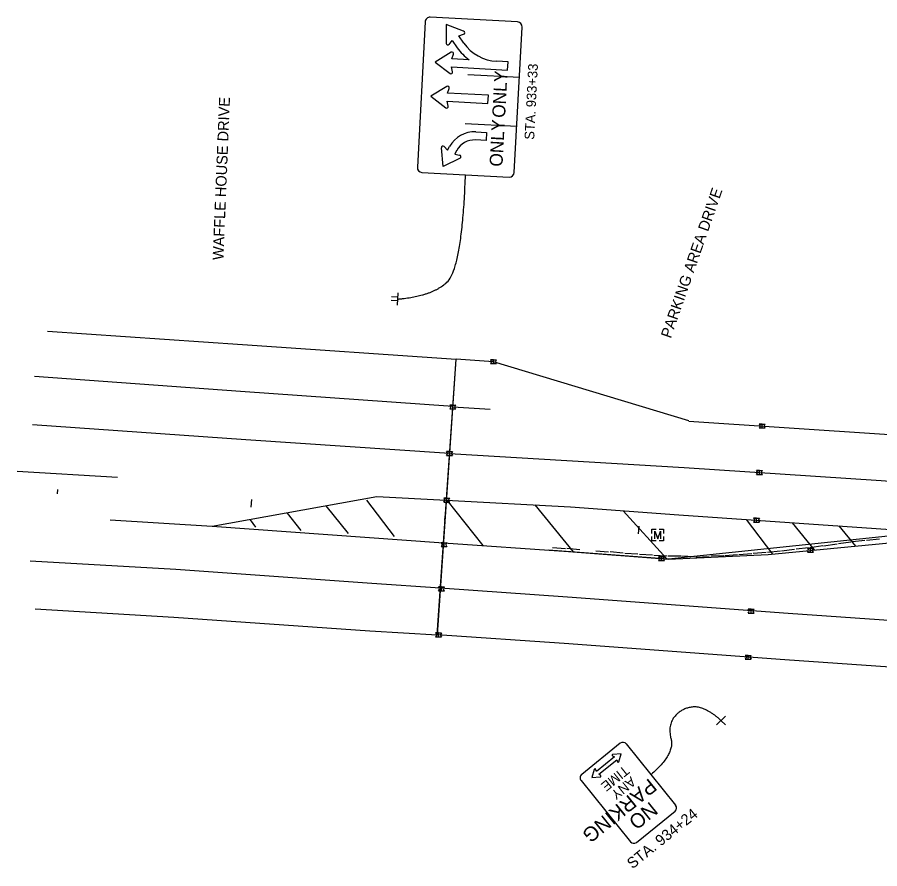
# Model space of a CAD drawing. Extents: x 1847379 to 1850904, y 217032 to 220169.
# Drawn here: x 1847379.5 to 1847601.7, y 218842.5 to 219061.8 of the extents above; entities that cross this region are included whole.
import ezdxf

# ---------------------------------------------------------------- set-up
doc = ezdxf.new("R2010")
doc.units = 0
for name, color, linetype in [('BR_P_Gen_Approach_Slab_Hidden', 7, 'Continuous'), ('BR_P_Gen_Phase_Construction', 7, 'Continuous'), ('GE_X_Alignment_100_Stations', 7, 'Continuous'), ('PM_P_Cells', 7, 'Continuous'), ('PM_P_Channelizing_Line', 7, 'Continuous'), ('PM_P_CL_Double_Solid', 7, 'Continuous'), ('PM_P_Edge_Line', 7, 'Continuous'), ('PM_P_Lane_Line', 7, 'Continuous'), ('PM_P_Transverse_Line', 7, 'Continuous'), ('PM_X_Channelizing_Line', 7, 'Continuous'), ('PM_X_CL_Double_Solid', 7, 'Continuous'), ('PM_X_Lane_Line', 7, 'Continuous'), ('PV_P_EOP', 7, 'Continuous'), ('RD_X_Bumper_Block', 7, 'Continuous'), ('SN_X_Public', 7, 'Continuous'), ('SN_X_Text', 7, 'Continuous'), ('SV_X_Mon_Cells_Found', 7, 'Continuous')]:
    doc.layers.add(name, color=color, linetype=linetype)

msp = doc.modelspace()

# ---------------------------------------------------------------- linework, layer by layer
at = {"layer": 'BR_P_Gen_Approach_Slab_Hidden'}
for p, q in [((1847387.24, 218980.94), (1847437.52, 218977.49)), ((1847437.52, 218977.49), (1847492.51, 218973.75)), ((1847384.1, 218909.4), (1847419.79, 218907.28)), ((1847419.79, 218907.28), (1847470.33, 218903.74)), ((1847470.33, 218903.74), (1847487.61, 218902.76))]:
    msp.add_line(p, q, dxfattribs=at)
at = {"layer": 'BR_P_Gen_Phase_Construction'}
msp.add_line((1847492.49, 218973.75), (1847487.63, 218902.76), dxfattribs=at)
at = {"layer": 'GE_X_Alignment_100_Stations'}
for p, q in [((1847389.87, 218939.01), (1847389.96, 218940.2)), ((1847439.76, 218935.59), (1847439.89, 218937.59)), ((1847489.64, 218932.18), (1847489.72, 218933.38)), ((1847539.53, 218928.77), (1847539.66, 218930.76))]:
    msp.add_line(p, q, dxfattribs=at)
at = {"layer": 'PM_P_Cells'}
for p, q in [((1847502.16, 218973.58), (1847501.38, 218973.58)), ((1847501.38, 218973.58), (1847502.16, 218973.58)), ((1847502.16, 218973.58), (1847502.93, 218973.58)), ((1847502.16, 218972.6), (1847502.16, 218973.58)), ((1847501.38, 218972.6), (1847502.16, 218972.6)), ((1847501.38, 218972.6), (1847502.16, 218972.6)), ((1847502.16, 218972.6), (1847502.93, 218972.6)), ((1847491.66, 218961.9), (1847490.89, 218961.9)), ((1847490.89, 218961.9), (1847491.66, 218961.9)), ((1847491.66, 218961.9), (1847492.43, 218961.9)), ((1847491.66, 218960.93), (1847491.66, 218961.9)), ((1847490.89, 218960.93), (1847491.66, 218960.93)), ((1847490.89, 218960.93), (1847491.66, 218960.93)), ((1847491.66, 218960.93), (1847492.43, 218960.93)), ((1847571.39, 218957), (1847570.62, 218957)), ((1847570.62, 218957), (1847571.39, 218957)), ((1847570.62, 218956.02), (1847571.39, 218956.02)), ((1847570.62, 218956.02), (1847571.39, 218956.02)), ((1847571.39, 218957), (1847572.16, 218957)), ((1847571.39, 218956.02), (1847571.39, 218957)), ((1847571.39, 218956.02), (1847572.16, 218956.02)), ((1847490.82, 218949.93), (1847490.05, 218949.93)), ((1847490.05, 218949.93), (1847490.82, 218949.93)), ((1847490.05, 218948.96), (1847490.82, 218948.96)), ((1847490.05, 218948.96), (1847490.82, 218948.96)), ((1847490.82, 218949.93), (1847491.59, 218949.93)), ((1847490.82, 218948.96), (1847490.82, 218949.93)), ((1847490.82, 218948.96), (1847491.59, 218948.96)), ((1847570.67, 218945.02), (1847569.9, 218945.02)), ((1847569.9, 218945.02), (1847570.67, 218945.02)), ((1847569.9, 218944.04), (1847570.67, 218944.04)), ((1847569.9, 218944.04), (1847570.67, 218944.04)), ((1847570.67, 218945.02), (1847571.44, 218945.02)), ((1847570.67, 218944.04), (1847570.67, 218945.02)), ((1847570.67, 218944.04), (1847571.44, 218944.04)), ((1847490.1, 218937.89), (1847489.33, 218937.89)), ((1847489.33, 218937.89), (1847490.1, 218937.89)), ((1847490.1, 218937.89), (1847490.87, 218937.89)), ((1847490.1, 218936.91), (1847490.1, 218937.89)), ((1847489.33, 218936.91), (1847490.1, 218936.91)), ((1847489.33, 218936.91), (1847490.1, 218936.91)), ((1847490.1, 218936.91), (1847490.87, 218936.91)), ((1847569.93, 218932.74), (1847569.16, 218932.74)), ((1847569.16, 218932.74), (1847569.93, 218932.74)), ((1847569.16, 218931.76), (1847569.93, 218931.76)), ((1847569.16, 218931.76), (1847569.93, 218931.76)), ((1847569.93, 218932.74), (1847570.7, 218932.74)), ((1847569.93, 218931.76), (1847569.93, 218932.74)), ((1847569.93, 218931.76), (1847570.7, 218931.76)), ((1847489.41, 218926.45), (1847488.64, 218926.45)), ((1847488.64, 218926.45), (1847489.41, 218926.45)), ((1847489.41, 218926.45), (1847490.18, 218926.45)), ((1847489.41, 218925.47), (1847489.41, 218926.45)), ((1847605.49, 218928.34), (1847547.23, 218922.25)), ((1847488.64, 218925.47), (1847489.41, 218925.47)), ((1847488.64, 218925.47), (1847489.41, 218925.47)), ((1847489.41, 218925.47), (1847490.18, 218925.47)), ((1847547.23, 218922.25), (1847516.32, 218924.55)), ((1847583.82, 218925.01), (1847583.05, 218925.01)), ((1847583.05, 218925.01), (1847583.82, 218925.01)), ((1847583.05, 218924.04), (1847583.82, 218924.04)), ((1847583.05, 218924.04), (1847583.82, 218924.04)), ((1847583.82, 218925.01), (1847584.59, 218925.01)), ((1847583.82, 218924.04), (1847583.82, 218925.01)), ((1847583.82, 218924.04), (1847584.59, 218924.04)), ((1847545.44, 218922.84), (1847544.67, 218922.84)), ((1847544.67, 218922.84), (1847545.44, 218922.84)), ((1847544.67, 218921.86), (1847545.44, 218921.86)), ((1847544.67, 218921.86), (1847545.44, 218921.86)), ((1847545.44, 218922.84), (1847546.21, 218922.84)), ((1847545.44, 218921.86), (1847545.44, 218922.84)), ((1847545.44, 218921.86), (1847546.21, 218921.86)), ((1847488.73, 218915.08), (1847487.96, 218915.08)), ((1847487.96, 218915.08), (1847488.73, 218915.08)), ((1847487.96, 218914.1), (1847488.73, 218914.1)), ((1847487.96, 218914.1), (1847488.73, 218914.1)), ((1847488.73, 218915.08), (1847489.5, 218915.08)), ((1847488.73, 218914.1), (1847488.73, 218915.08)), ((1847488.73, 218914.1), (1847489.5, 218914.1)), ((1847568.53, 218909.31), (1847567.76, 218909.31)), ((1847567.76, 218909.31), (1847568.53, 218909.31)), ((1847568.53, 218909.31), (1847569.3, 218909.31)), ((1847568.53, 218908.33), (1847568.53, 218909.31)), ((1847567.76, 218908.33), (1847568.53, 218908.33)), ((1847567.76, 218908.33), (1847568.53, 218908.33)), ((1847568.53, 218908.33), (1847569.3, 218908.33)), ((1847488.02, 218903.22), (1847487.25, 218903.22)), ((1847487.25, 218903.22), (1847488.02, 218903.22)), ((1847487.25, 218902.24), (1847488.02, 218902.24)), ((1847487.25, 218902.24), (1847488.02, 218902.24)), ((1847488.02, 218903.22), (1847488.79, 218903.22)), ((1847488.02, 218902.24), (1847488.02, 218903.22)), ((1847488.02, 218902.24), (1847488.79, 218902.24)), ((1847567.81, 218897.45), (1847567.04, 218897.45)), ((1847567.04, 218897.45), (1847567.81, 218897.45)), ((1847567.81, 218897.45), (1847568.58, 218897.45)), ((1847567.81, 218896.47), (1847567.81, 218897.45)), ((1847567.04, 218896.47), (1847567.81, 218896.47)), ((1847567.04, 218896.47), (1847567.81, 218896.47)), ((1847567.81, 218896.47), (1847568.58, 218896.47))]:
    msp.add_line(p, q, dxfattribs=at)
for centre, start, end in [((1847501.08, 218973.09), 301.9738, 58.0262), ((1847501.08, 218973.09), 301.9738, 58.0262), ((1847503.23, 218973.09), 121.9738, 238.0262), ((1847490.59, 218961.41), 301.9738, 58.0262), ((1847490.59, 218961.41), 301.9738, 58.0262), ((1847492.74, 218961.41), 121.9738, 238.0262), ((1847570.32, 218956.51), 301.9738, 58.0262), ((1847570.32, 218956.51), 301.9738, 58.0262), ((1847572.47, 218956.51), 121.9738, 238.0262), ((1847489.75, 218949.44), 301.9738, 58.0262), ((1847489.75, 218949.44), 301.9738, 58.0262), ((1847491.9, 218949.44), 121.9738, 238.0262), ((1847569.6, 218944.53), 301.9738, 58.0262), ((1847569.6, 218944.53), 301.9738, 58.0262), ((1847571.75, 218944.53), 121.9738, 238.0262), ((1847489.02, 218937.4), 301.9738, 58.0262), ((1847489.02, 218937.4), 301.9738, 58.0262), ((1847491.18, 218937.4), 121.9738, 238.0262), ((1847568.86, 218932.25), 301.9738, 58.0262), ((1847568.86, 218932.25), 301.9738, 58.0262), ((1847571.01, 218932.25), 121.9738, 238.0262), ((1847488.34, 218925.96), 301.9738, 58.0262), ((1847488.34, 218925.96), 301.9738, 58.0262), ((1847490.49, 218925.96), 121.9738, 238.0262), ((1847582.74, 218924.52), 301.9738, 58.0262), ((1847582.74, 218924.52), 301.9738, 58.0262), ((1847584.89, 218924.52), 121.9738, 238.0262), ((1847544.36, 218922.35), 301.9738, 58.0262), ((1847544.36, 218922.35), 301.9738, 58.0262), ((1847546.51, 218922.35), 121.9738, 238.0262), ((1847487.65, 218914.59), 301.9738, 58.0262), ((1847487.65, 218914.59), 301.9738, 58.0262), ((1847489.8, 218914.59), 121.9738, 238.0262), ((1847567.45, 218908.82), 301.9738, 58.0262), ((1847567.45, 218908.82), 301.9738, 58.0262), ((1847569.6, 218908.82), 121.9738, 238.0262), ((1847486.94, 218902.73), 301.9738, 58.0262), ((1847486.94, 218902.73), 301.9738, 58.0262), ((1847489.09, 218902.73), 121.9738, 238.0262), ((1847566.74, 218896.96), 301.9738, 58.0262), ((1847566.74, 218896.96), 301.9738, 58.0262), ((1847568.89, 218896.96), 121.9738, 238.0262)]:
    msp.add_arc(centre, 0.576, start, end, dxfattribs=at)
at = {"layer": 'PM_P_Channelizing_Line'}
msp.add_line((1847501.31, 218960.76), (1847491.66, 218961.41), dxfattribs=at)
at = {"layer": 'PM_P_CL_Double_Solid'}
for points in [[(1847490, 218937.41), (1847521.99, 218935.72), (1847549.87, 218933.62), (1847611.92, 218929.38), (1847659.1, 218926.63), (1847712.21, 218923.52), (1847759.64, 218920.72), (1847810.63, 218918.2), (1847858.38, 218915.68), (1847905.32, 218913.72), (1847953.04, 218910.96), (1847965.57, 218910.45)], [(1847489.25, 218926.47), (1847521.5, 218924.19), (1847547.23, 218922.25), (1847572.89, 218923.43), (1847613.93, 218927.4), (1847658.9, 218924.58), (1847711.95, 218921.4), (1847759.89, 218918.36), (1847810.62, 218915.58), (1847858.37, 218912.98), (1847905.65, 218910.62), (1847953.25, 218908.34), (1847965.4, 218907.5)]]:
    msp.add_lwpolyline(points, dxfattribs=at)
at = {"layer": 'PM_P_Edge_Line'}
for p, q in [((1847502.16, 218973.09), (1847492.51, 218973.75)), ((1847552.48, 218957.86), (1847502.16, 218973.09))]:
    msp.add_line(p, q, dxfattribs=at)
for points in [[(1847552.47, 218957.76), (1847602.87, 218954.43), (1847648.99, 218950.94), (1847698.22, 218948.16), (1847749.1, 218945.08), (1847799.04, 218942.57), (1847847.68, 218940.46), (1847895.74, 218937.94), (1847929.69, 218936.33), (1847972.19, 218934.13)], [(1847963.46, 218872.86), (1847915.07, 218875.36), (1847912.14, 218875.67), (1847866.67, 218878.08), (1847793.75, 218882.07), (1847746.55, 218884.86), (1847706.33, 218887.44), (1847651.18, 218890.91), (1847631.45, 218892.5), (1847577.19, 218896.26), (1847520.38, 218900.5), (1847487.61, 218902.76)]]:
    msp.add_lwpolyline(points, dxfattribs=at)
at = {"layer": 'PM_P_Lane_Line'}
for points in [[(1847490.83, 218949.44), (1847551.31, 218945.81), (1847602.03, 218942.46), (1847648.2, 218938.97), (1847697.52, 218936.18), (1847748.44, 218933.1), (1847798.48, 218930.58), (1847847.11, 218928.48), (1847895.15, 218925.96), (1847929.1, 218924.34), (1847971.57, 218922.14)], [(1847964.08, 218884.84), (1847916.01, 218887.33), (1847913.09, 218887.64), (1847867.32, 218890.07), (1847794.43, 218894.05), (1847747.29, 218896.84), (1847707.09, 218899.42), (1847652.04, 218902.88), (1847632.34, 218904.47), (1847578.05, 218908.23), (1847521.24, 218912.47), (1847488.44, 218914.73)]]:
    msp.add_lwpolyline(points, dxfattribs=at)
at = {"layer": 'PM_P_Transverse_Line'}
for p, q in [((1847499.5, 218925.74), (1847490.19, 218937.4)), ((1847522.79, 218924.09), (1847512.87, 218936.2)), ((1847546.82, 218922.28), (1847535.54, 218934.7)), ((1847574.16, 218923.55), (1847567.32, 218932.43)), ((1847584.87, 218924.59), (1847579.2, 218931.62)), ((1847595.49, 218925.61), (1847591.25, 218930.79))]:
    msp.add_line(p, q, dxfattribs=at)
at = {"layer": 'PM_X_Channelizing_Line'}
for points in [[(1847383.91, 218969.34), (1847436.97, 218965.46), (1847491.68, 218961.61)], [(1847405.3, 218943.24), (1847379.47, 218944.84)]]:
    msp.add_lwpolyline(points, dxfattribs=at)
at = {"layer": 'PM_X_CL_Double_Solid'}
for points in [[(1847429.7, 218930.69), (1847472.11, 218938.35), (1847490, 218937.41)], [(1847476.63, 218928.1), (1847469.56, 218937.46)], [(1847464.77, 218928.8), (1847459.01, 218935.93)], [(1847452.6, 218929.59), (1847449.06, 218934.06)], [(1847403.38, 218932.37), (1847429.67, 218930.69), (1847489.25, 218926.47)], [(1847440.94, 218930.5), (1847439.56, 218932.35)]]:
    msp.add_lwpolyline(points, dxfattribs=at)
at = {"layer": 'PM_X_Lane_Line'}
for points in [[(1847383.39, 218956.93), (1847438.38, 218953.07), (1847490.84, 218949.53)], [(1847488.44, 218914.73), (1847470.8, 218915.95), (1847420.35, 218919.52), (1847382.82, 218921.68)]]:
    msp.add_lwpolyline(points, dxfattribs=at)
at = {"layer": 'PV_P_EOP'}
msp.add_line((1847487.61, 218902.76), (1847492.51, 218973.75), dxfattribs=at)
at = {"layer": 'RD_X_Bumper_Block'}
for points in [[(1847594.23, 218926.6), (1847591.03, 218926.2)], [(1847597.85, 218927.07), (1847594.65, 218926.66)], [(1847601.57, 218927.34), (1847598.25, 218927.04)], [(1847517.4, 218925.24), (1847520.73, 218924.95)], [(1847524.39, 218924.66), (1847521.08, 218925)], [(1847531.82, 218924.06), (1847528.54, 218924.32)], [(1847535.57, 218923.76), (1847532.23, 218924.11)], [(1847576.09, 218924.31), (1847572.79, 218923.95)], [(1847579.68, 218924.7), (1847576.38, 218924.28)], [(1847583.34, 218925.14), (1847580.11, 218924.81)], [(1847586.99, 218925.66), (1847583.64, 218925.18)], [(1847590.73, 218926.07), (1847587.21, 218925.61)], [(1847539.35, 218923.49), (1847536.02, 218923.71)], [(1847543.13, 218923.22), (1847539.74, 218923.41)], [(1847546.81, 218923.02), (1847543.44, 218923.19)], [(1847550.4, 218922.96), (1847547.06, 218922.98)], [(1847553.95, 218922.83), (1847550.6, 218923.02)], [(1847557.75, 218922.8), (1847554.31, 218922.68)], [(1847561.5, 218923.06), (1847558.17, 218922.97)], [(1847565.06, 218923.34), (1847561.78, 218923.12)], [(1847568.75, 218923.6), (1847565.4, 218923.32)], [(1847572.4, 218923.92), (1847569.09, 218923.66)]]:
    msp.add_lwpolyline(points, dxfattribs=at)
at = {"layer": 'SN_X_Public'}
for p, q in [((1847494.47, 219058.21), (1847489.94, 219059.91)), ((1847489.94, 219059.91), (1847489.97, 219055.08)), ((1847493.22, 219057.04), (1847494.44, 219057.42)), ((1847490.72, 219054.82), (1847491.51, 219055.84)), ((1847491.51, 219055.84), (1847492.82, 219053.96)), ((1847494.53, 219055.15), (1847493.22, 219057.04)), ((1847491.25, 219052.78), (1847487.13, 219050.25)), ((1847491.41, 219051.07), (1847491.86, 219052.28)), ((1847495.91, 219050.83), (1847491.41, 219051.07)), ((1847487.13, 219050.25), (1847490.96, 219047.31)), ((1847491.62, 219047.74), (1847491.3, 219048.99)), ((1847491.3, 219048.99), (1847505.79, 219048.21)), ((1847505.91, 219050.29), (1847502.99, 219050.45)), ((1847505.79, 219048.21), (1847505.91, 219050.29)), ((1847495.51, 219047.04), (1847508.82, 219046.33)), ((1847490.15, 219043.97), (1847486.03, 219041.45)), ((1847490.31, 219042.26), (1847490.76, 219043.47)), ((1847500.85, 219041.69), (1847490.31, 219042.26)), ((1847486.03, 219041.45), (1847489.86, 219038.5)), ((1847490.52, 219038.93), (1847490.2, 219040.18)), ((1847490.2, 219040.18), (1847500.74, 219039.61)), ((1847500.74, 219039.61), (1847500.85, 219041.69)), ((1847494.83, 219034.45), (1847508.15, 219033.74)), ((1847497.64, 219032.27), (1847500.34, 219032.13)), ((1847500.34, 219032.13), (1847500.23, 219030.05)), ((1847489.44, 219028.47), (1847490.34, 219027.55)), ((1847490.34, 219027.55), (1847490.84, 219028.47)), ((1847500.23, 219030.05), (1847497.52, 219030.19)), ((1847489.23, 219023.33), (1847488.73, 219028.14)), ((1847492.67, 219027.48), (1847492.17, 219026.55)), ((1847492.17, 219026.55), (1847493.43, 219026.3)), ((1847493.54, 219025.52), (1847489.23, 219023.33)), ((1847477.52, 218990.81), (1847477.32, 218987.61)), ((1847477.39, 218988.73), (1847475.79, 218988.83)), ((1847477.45, 218989.69), (1847475.85, 218989.79)), ((1847477.42, 218989.21), (1847477.42, 218989.21)), ((1847559.63, 218879.57), (1847561.91, 218881.82)), ((1847560.77, 218880.7), (1847561.89, 218879.55)), ((1847532.82, 218871.6), (1847533.32, 218871.27)), ((1847535.07, 218872.08), (1847532.91, 218871.94)), ((1847534.47, 218870), (1847535.07, 218872.08)), ((1847529.28, 218866.81), (1847533.91, 218870.54)), ((1847531.29, 218869.04), (1847531.29, 218869.04)), ((1847533.91, 218870.54), (1847533.9, 218870.54)), ((1847533.91, 218870.54), (1847534.12, 218869.98)), ((1847528.12, 218868.08), (1847527.52, 218866)), ((1847528.68, 218867.54), (1847528.47, 218868.09)), ((1847529.77, 218866.48), (1847529.27, 218866.81)), ((1847529.27, 218866.81), (1847529.28, 218866.81)), ((1847527.52, 218866), (1847529.68, 218866.14))]:
    msp.add_line(p, q, dxfattribs=at)
for points in [[(1847508.34, 219060.59), (1847485.87, 219061.8)], [(1847484.55, 219060.62), (1847482.54, 219023.17)], [(1847507.51, 219021.83), (1847509.52, 219059.28)], [(1847483.72, 219021.85), (1847506.19, 219020.65)], [(1847534.81, 218874.79), (1847524.88, 218866.79)], [(1847549.1, 218858.86), (1847536.39, 218874.62)], [(1847533.32, 218871.27), (1847528.69, 218867.54)], [(1847524.71, 218865.21), (1847537.42, 218849.44)], [(1847539, 218849.27), (1847548.93, 218857.28)]]:
    msp.add_lwpolyline(points, dxfattribs=at)
for centre, radius, start, end in [((1847485.8, 219060.55), 1.25, 86.9284, 176.9284), ((1847508.27, 219059.34), 1.25, 356.9284, 86.9284), ((1847494.32, 219057.82), 0.417, 287.5523, 69.4304), ((1847503.58, 219061.47), 11.04, 214.9141, 266.9284), ((1847490.39, 219055.08), 0.417, 180.3978, 322.2759), ((1847503.58, 219061.47), 13.12, 214.9141, 234.2028), ((1847491.47, 219052.42), 0.417, 339.5666, 121.4447), ((1847491.21, 219047.64), 0.417, 232.4121, 14.2902), ((1847490.37, 219043.61), 0.417, 339.5666, 121.4447), ((1847490.11, 219038.83), 0.417, 232.4121, 14.2902), ((1847497.25, 219024.99), 7.29, 86.9284, 151.4457), ((1847489.14, 219028.18), 0.417, 44.0839, 185.962), ((1847497.25, 219024.99), 5.21, 86.9284, 151.4457), ((1847493.35, 219025.89), 0.417, 296.9294, 78.8075), ((1847483.79, 219023.1), 1.25, 176.9284, 266.9284), ((1847506.26, 219021.9), 1.25, 266.9284, 356.9284), ((1847535.51, 218873.92), 1.12, 38.8676, 128.8676), ((1847532.92, 218871.75), 0.182, 93.7884, 236.5054), ((1847534.29, 218870.05), 0.182, 201.2298, 343.9469), ((1847525.59, 218865.92), 1.12, 128.8676, 218.8676), ((1847528.3, 218868.03), 0.182, 21.2298, 163.9469), ((1847529.67, 218866.32), 0.182, 273.7884, 56.5054), ((1847548.22, 218858.15), 1.12, 308.8676, 38.8676), ((1847538.29, 218850.15), 1.12, 218.8676, 308.8676)]:
    msp.add_arc(centre, radius, start, end, dxfattribs=at)
for points in [[(1847477.42, 218989.21), (1847486.3, 218989.92), (1847494.06, 218997.21), (1847494.96, 219021.25)], [(1847560.77, 218880.7), (1847556.48, 218884.44), (1847550.67, 218883.88), (1847546.96, 218879.45), (1847548.88, 218872.11), (1847542.74, 218866.74)]]:
    msp.add_open_spline(points, degree=2, dxfattribs=at)
at = {"layer": 'SV_X_Mon_Cells_Found'}
msp.add_line((1847544.47, 218928.43), (1847544.47, 218928.43), dxfattribs=at)
msp.add_line((1847544.47, 218928.43), (1847544.47, 218928.43), dxfattribs=at)
for points in [[(1847542.97, 218928.81), (1847542.97, 218929.93), (1847544.09, 218929.93)], [(1847542.97, 218928.81), (1847542.97, 218929.93), (1847544.09, 218929.93)], [(1847543.73, 218927.43), (1847543.73, 218929.43), (1847544.47, 218927.43), (1847545.21, 218929.43), (1847545.21, 218927.43)], [(1847543.73, 218927.43), (1847543.73, 218929.43), (1847544.47, 218927.43), (1847545.21, 218929.43), (1847545.21, 218927.43)], [(1847544.82, 218929.93), (1847545.97, 218929.93), (1847545.97, 218928.81)], [(1847544.82, 218929.93), (1847545.97, 218929.93), (1847545.97, 218928.81)], [(1847544.09, 218926.93), (1847542.97, 218926.93), (1847542.97, 218928.05)], [(1847544.09, 218926.93), (1847542.97, 218926.93), (1847542.97, 218928.05)], [(1847545.97, 218928.05), (1847545.97, 218926.93), (1847544.82, 218926.93)], [(1847545.97, 218928.05), (1847545.97, 218926.93), (1847544.82, 218926.93)]]:
    msp.add_lwpolyline(points, dxfattribs=at)

# ---------------------------------------------------------------- texts
at = {"layer": 'SN_X_Public'}
for s, height, rotation, p in [('ONLY', 3.333, 86.9284, (1847505.13, 219035.83)), ('WAFFLE HOUSE DRIVE', 2.8, 87.6718, (1847432.58, 218999.21)), ('ONLY', 3.333, 86.9284, (1847504.45, 219023.25)), ('PARKING AREA DRIVE', 2.8, 70.7779, (1847547.83, 218978.93)), ('TIME', 2.5, 218.8676, (1847535.84, 218869.2)), ('ANY', 2.5, 218.8676, (1847537.55, 218866.37)), ('PARKING', 3.75, 218.8676, (1847542.26, 218865.95)), ('NO', 3.75, 218.8676, (1847542.51, 218859.93)), ('STA. 934+24', 2.8, 38.8676, (1847537.95, 218842.31))]:
    msp.add_text(s, height=height, rotation=rotation, dxfattribs=at).set_placement(p)
at = {"layer": 'SN_X_Text'}
msp.add_text('STA. 933+33', height=2.5, rotation=87.1408, dxfattribs=at).set_placement((1847512.64, 219030.21))

doc.saveas('drawing.dxf')
